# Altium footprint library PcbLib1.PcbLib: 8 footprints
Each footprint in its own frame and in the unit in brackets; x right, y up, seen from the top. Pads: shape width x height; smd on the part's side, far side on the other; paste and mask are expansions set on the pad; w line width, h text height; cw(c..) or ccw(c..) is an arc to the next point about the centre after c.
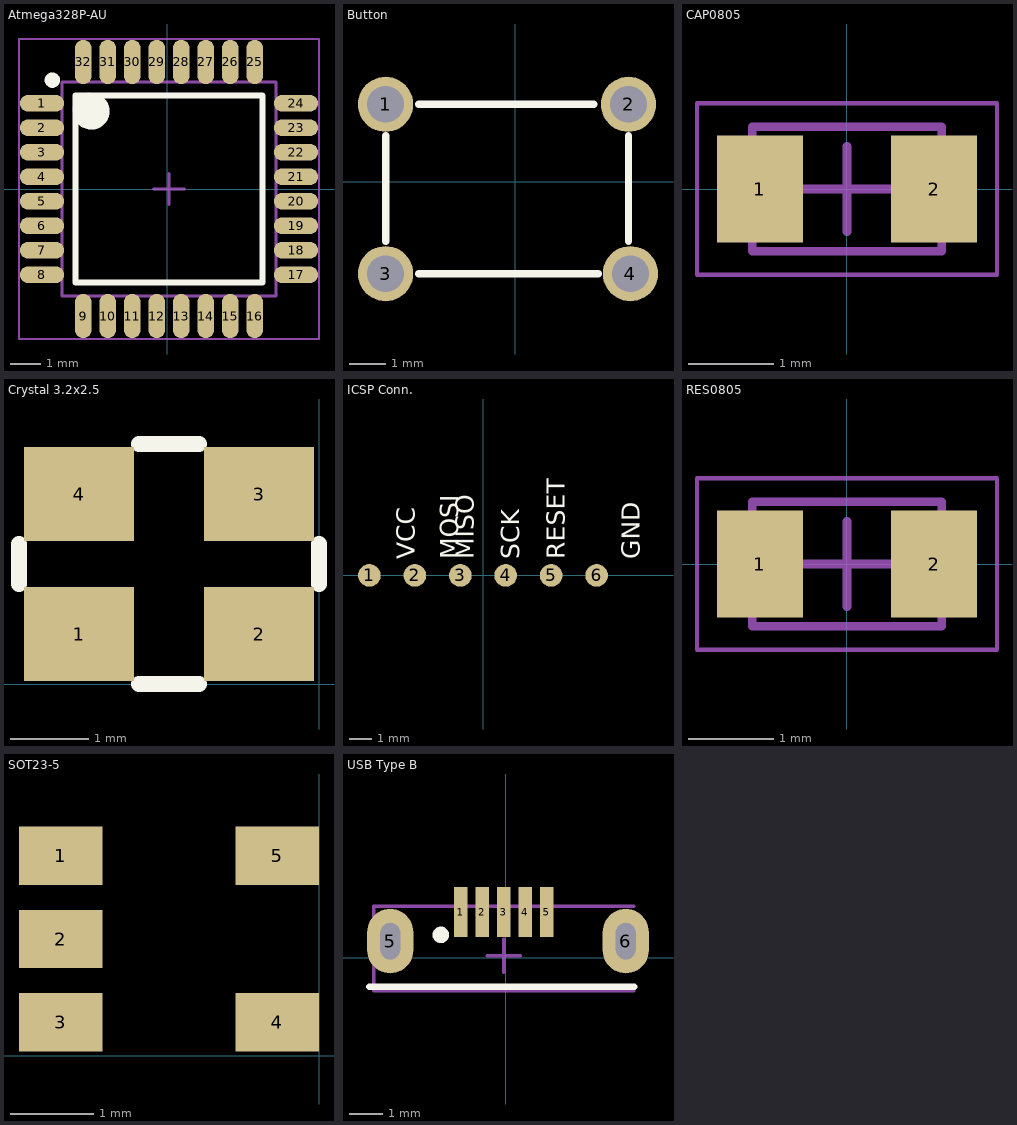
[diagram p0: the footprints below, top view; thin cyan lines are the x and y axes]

## Atmega328P-AU [mm]
pads (32):
  oval 1.45x0.55 smd: 1(-4.1,2.8) 2(-4.1,2) 3(-4.1,1.2) 4(-4.1,0.4) 5(-4.1,-0.4) 6(-4.1,-1.2) 7(-4.1,-2) 8(-4.1,-2.8) 17(4.2,-2.8) 18(4.2,-2) 19(4.2,-1.2) 20(4.2,-0.4) 21(4.2,0.4) 22(4.2,1.2) 23(4.2,2) 24(4.2,2.8)
  oval 0.55x1.45 smd: 9(-2.75,-4.15) 10(-1.95,-4.15) 11(-1.15,-4.15) 12(-0.35,-4.15) 13(0.45,-4.15) 14(1.25,-4.15) 15(2.05,-4.15) 16(2.85,-4.15) 25(2.85,4.15) 26(2.05,4.15) 27(1.25,4.15) 28(0.45,4.15) 29(-0.35,4.15) 30(-1.15,4.15) 31(-1.95,4.15) 32(-2.75,4.15)
Top Overlay:
  circle w0.25: c-3.76,3.556 r0.125
  circle w0.6: c-2.49,2.54 r0.3
  lines w0.2: -3,-3.05 -3,3.05 3.1,3.05 3.1,-3.05 -3,-3.05
Mechanical 13:
  circle w0.1: c-2.55,2.6 r0.5
  lines w0.1: -3.45,-3.5 -3.45,3.5 3.55,3.5 3.55,-3.5 -3.45,-3.5
Mechanical 15:
  lines w0.05: -4.85,-4.9 -4.85,4.9 4.95,4.9 4.95,-4.9 -4.85,-4.9
  lines w0.1: -0.45,0 0.55,0 ; 0.05,-0.5 0.05,0.5
3D body "User Library-TQFP-32.STEP": height 1.45, standoff -0.01, extent -4.45,-4.5 4.55,4.5
3D body: height 1.45, standoff 0, extent 0.05,0 0.05,0
3D body: height 1.45, standoff 0, extent 0.05,0 0.05,0

## Button [mm]
pads (4):
  round 1.5 hole 1: 1(-3.525,2.1) 2(3.075,2.1) 3(-3.525,-2.5) 4(3.125,-2.5)
Top Overlay:
  lines w0.2: -3.525,-1.625 -3.525,1.25 ; -2.625,-2.5 2.25,-2.5 ; -2.625,2.1 2.125,2.1 ; 3.075,-1.625 3.075,1.25

## CAP0805 [mm]
pads (2):
  rect 1x1.25 smd: 1(-1.016,0) 2(1.016,0)
Mechanical 13:
  lines w0.1: -1.105,-0.725 1.105,-0.725 1.105,0.725 -1.105,0.725 -1.105,-0.725
Mechanical 15:
  lines w0.05: -1.75,-1 1.75,-1 1.75,1 -1.75,1 -1.75,-1
  lines w0.1: -0.5,0 0.5,0 ; 0,-0.5 0,0.5
3D body: height 0.94, standoff 0, extent 0.605,-0.725 1.105,0.725
3D body: height 0.94, standoff 0, extent -1.105,-0.725 -0.605,0.725
3D body: height 0.94, standoff 0, extent -0.605,-0.725 0.605,0.725

## Crystal 3.2x2.5 [mm]
pads (4):
  rect 1.4x1.2 smd: 1(-3.048,0.635) 2(-0.762,0.635) 3(-0.762,2.413) 4(-3.048,2.413)
Top Overlay:
  lines w0.2: -3.81,1.27 -3.81,1.778 ; -2.286,0 -1.524,0 ; -2.286,3.048 -1.524,3.048 ; 0,1.27 0,1.778
3D body "User Library-Crystal_ECX-32.STEP": height 0.82, standoff 0, extent -3.505,0.274 -0.305,2.774
3D body: height 1.35, standoff 0, extent -1.905,1.524 -1.905,1.524
3D body: height 1.35, standoff 0, extent -3.302,2.54 -3.302,2.54

## ICSP Conn. [mm]
pads (6):
  round 1 smd: 1(-5,0) 2(-3,0) 3(-1,0) 4(1,0) 5(3,0) 6(5,0)
Top Overlay:
  text "RESET" at 3.6,0.7 h0.8
  text "SCK" at 1.6,0.7 h0.8
  text "GND" at 6.9,0.7 h0.8
  text "MISO" at -0.4,0.7 h0.8
  text "MOSI" at -1.1,0.7 h0.8
  text "VCC" at -3,0.7 h0.8

## RES0805 [mm]
pads (2):
  rect 1x1.25 smd: 1(-1.016,0) 2(1.016,0)
Mechanical 13:
  lines w0.1: -1.105,-0.725 -1.105,0.725 1.105,0.725 1.105,-0.725 -1.105,-0.725
Mechanical 15:
  lines w0.05: -1.75,-1 -1.75,1 1.75,1 1.75,-1 -1.75,-1
  lines w0.1: -0.5,0 0.5,0 ; 0,-0.5 0,0.5
3D body: height 0.94, standoff 0, extent -0.605,-0.725 0.605,0.725
3D body: height 0.94, standoff 0, extent -1.105,-0.725 -0.605,0.725
3D body: height 0.94, standoff 0, extent 0.605,-0.725 1.105,0.725

## SOT23-5 [mm]
pads (5):
  rect 1x0.7 smd: 1(-3.1,2.4) 2(-3.1,1.4) 3(-3.1,0.4) 4(-0.5,0.4) 5(-0.5,2.4)

## USB Type B [mm]
pads (7):
  rect 0.4x1.5 smd: 1(-1.364,1.381) 2(-0.714,1.381) 3(-0.064,1.381) 4(0.586,1.381) 5(1.236,1.381)
  oval 1.4x1.95 hole 1.1 slot 0.6 at 0 deg: 5(-3.5,0.5) 6(3.625,0.5)
Top Overlay:
  circle w0.25: c-1.969,0.691 r0.125
  lines w0.2: -4.128,-0.875 3.875,-0.875
Mechanical 13:
  lines w0.1: 3.875,-1 -3.994,-1 -3.994,1.556 3.875,1.556
Mechanical 15:
  lines w0.1: -0.564,0.056 0.436,0.056 ; -0.064,-0.444 -0.064,0.556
